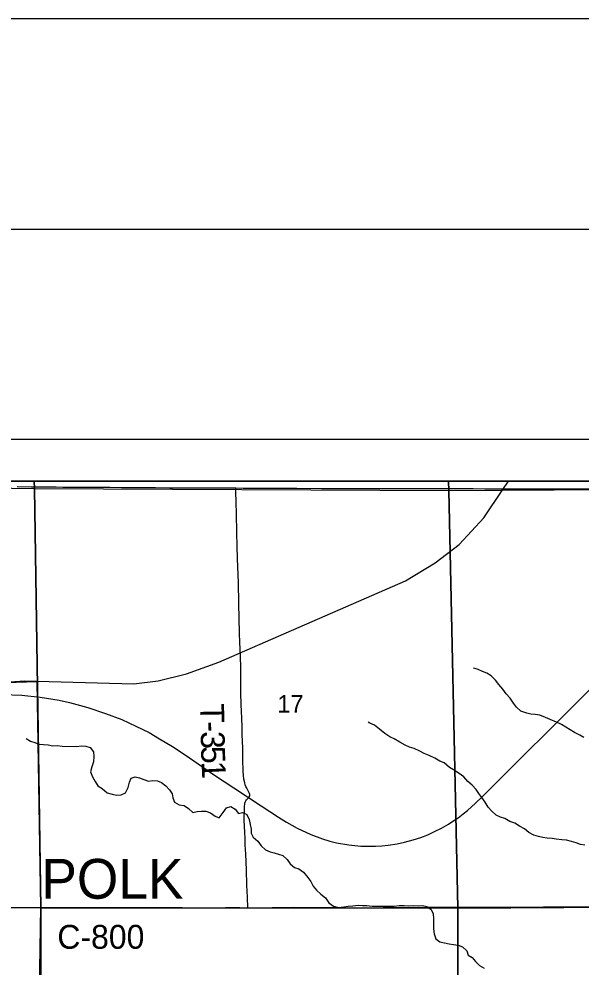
# Model space of a CAD drawing. Extents: x 0 to 34, y 0 to 22.
# Drawn here: x 4.028 to 5.364, y 19.744 to 22 of the extents above; entities that cross this region are included whole.
import ezdxf

# ---------------------------------------------------------------- set-up
doc = ezdxf.new("R2010")
doc.units = 0
for name, color, linetype in [('Default', 7, 'Continuous'), ('GM_X_Corporation', 7, 'Continuous'), ('GM_X_Corporation_Text', 7, 'Continuous'), ('GM_X_County_Road', 7, 'Continuous'), ('GM_X_County_Road_Text', 7, 'Continuous'), ('GM_X_Interstate_Route', 7, 'Continuous'), ('GM_X_Minor_River', 7, 'Continuous'), ('GM_X_Rail_Line', 7, 'Continuous'), ('GM_X_Section', 7, 'Continuous'), ('GM_X_Section_Text', 7, 'Continuous'), ('GM_X_Township_Road', 7, 'Continuous'), ('GM_X_Township_Road_Text', 7, 'Continuous'), ('SH_Border', 7, 'Continuous'), ('SH_Cut_Line', 7, 'Continuous'), ('SH_Data', 7, 'Continuous')]:
    doc.layers.add(name, color=color, linetype=linetype)

msp = doc.modelspace()

# ---------------------------------------------------------------- linework, layer by layer
at = {"layer": 'Default'}
for points in [[(4.0643, 20.9), (3.0341, 20.9), (3.0341, 20.898), (4.0647, 20.8827)], [(5.0488, 20.9), (4.0643, 20.9), (4.0647, 20.8827), (5.0494, 20.8782)], [(6.0512, 20.9), (5.0488, 20.9), (5.0494, 20.8782), (6.0515, 20.8843)]]:
    msp.add_lwpolyline(points, close=True, dxfattribs=at)
at = {"layer": 'GM_X_Corporation'}
msp.add_lwpolyline([(4.0712, 19.394), (3.5643, 19.3915), (3.0631, 19.3888), (3.0588, 19.9042), (3.0542, 20.415), (3.5567, 20.4072), (4.0701, 20.4238), (4.0786, 19.8867)], close=True, dxfattribs=at)
at = {"layer": 'GM_X_County_Road'}
for points in [[(4.0234, 20.8873), (4.0575, 20.8869), (4.0855, 20.8867), (4.1166, 20.8864), (4.1321, 20.8862), (4.1693, 20.8858), (4.2004, 20.8857), (4.2439, 20.8856), (4.2718, 20.8852), (4.2967, 20.885), (4.334, 20.8848), (4.3526, 20.8848), (4.3867, 20.8847), (4.4054, 20.8846), (4.4458, 20.8845), (4.5017, 20.8842), (4.5265, 20.8843), (4.5433, 20.8841)], [(4.5433, 20.8841), (4.5607, 20.8839), (4.5886, 20.8836), (4.6104, 20.8836), (4.6352, 20.8837), (4.688, 20.8832), (4.747, 20.883), (4.7905, 20.883), (4.8185, 20.8829), (4.8682, 20.8827), (4.9085, 20.8829), (4.9396, 20.8827), (5.0017, 20.8825), (5.0794, 20.8828), (5.1073, 20.8826), (5.1353, 20.8822), (5.1602, 20.8822), (5.1819, 20.882), (5.2005, 20.8819), (5.2316, 20.8823), (5.2595, 20.8823), (5.2968, 20.8822), (5.3403, 20.8821), (5.3838, 20.8819)], [(3.5641, 19.886), (3.5756, 19.8859), (3.5943, 19.886), (3.6161, 19.8861), (3.6566, 19.8863), (3.7251, 19.8868), (3.7624, 19.8868), (3.7935, 19.8869), (3.834, 19.8871), (3.8776, 19.8872), (3.9118, 19.8871), (3.9803, 19.8869), (4.0788, 19.8862)], [(4.0788, 19.8862), (4.0963, 19.8861), (4.1398, 19.8859), (4.1615, 19.8859), (4.2018, 19.886), (4.2422, 19.8859), (4.2981, 19.8859), (4.3756, 19.8855), (4.416, 19.8855), (4.478, 19.8854), (4.5184, 19.8855), (4.5525, 19.8855), (4.5719, 19.8854)], [(4.5719, 19.8854), (4.5835, 19.8853), (4.63, 19.886), (4.6797, 19.8866), (4.7944, 19.886), (4.8503, 19.8854), (4.8937, 19.8856), (4.9272, 19.8858), (4.9706, 19.886), (4.9955, 19.8863), (5.0141, 19.8864), (5.0482, 19.8864), (5.0698, 19.8867), (5.1008, 19.8866), (5.135, 19.8867), (5.166, 19.8869), (5.1847, 19.8868), (5.2747, 19.8873), (5.3057, 19.8876), (5.3243, 19.8876), (5.3491, 19.8875), (5.3771, 19.8876), (5.3988, 19.8875), (5.4225, 19.8877)]]:
    msp.add_lwpolyline(points, dxfattribs=at)
at = {"layer": 'GM_X_Interstate_Route'}
msp.add_lwpolyline([(8.1285, 16.8707), (8.1148, 17.8694), (8.0976, 18.2853), (8.0958, 18.3144), (8.0817, 18.88), (8.0959, 19.2713), (8.1023, 19.3817), (8.0929, 19.6339), (8.0678, 20.8562), (8.0675, 20.8733), (8.067, 20.8954), (8.0669, 20.9), (3.0331, 20.9), (3.0588, 19.9042), (3.067, 19.3838), (3.0747, 18.8969), (3.0724, 18.2926), (3.0939, 16.8719)], dxfattribs=at)
at = {"layer": 'GM_X_Minor_River'}
for points in [[(5.371, 20.2903), (5.3612, 20.2957), (5.3488, 20.3022), (5.3378, 20.3088), (5.3175, 20.3211), (5.3054, 20.3266), (5.2903, 20.3332), (5.2798, 20.3378), (5.2662, 20.3433), (5.2548, 20.3449), (5.2446, 20.3458), (5.2348, 20.3485), (5.2208, 20.3528), (5.2103, 20.3624), (5.2036, 20.372), (5.1957, 20.3842), (5.186, 20.3945), (5.1785, 20.4056), (5.1687, 20.4163), (5.1605, 20.427), (5.1503, 20.437), (5.1398, 20.4431), (5.1296, 20.4474), (5.1194, 20.4524), (5.1092, 20.4556), (5.1085, 20.4563)], [(5.373, 20.0338), (5.3628, 20.0358), (5.3526, 20.0397), (5.3416, 20.0428), (5.3292, 20.0463), (5.3182, 20.0472), (5.3053, 20.0488), (5.2951, 20.0501), (5.2837, 20.0509), (5.2732, 20.0522), (5.2633, 20.0546), (5.2516, 20.0577), (5.2403, 20.0639), (5.2294, 20.0727), (5.2181, 20.0793), (5.2068, 20.0862), (5.1947, 20.0901), (5.183, 20.0975), (5.1728, 20.101), (5.1619, 20.1056), (5.1518, 20.1148), (5.1435, 20.1244), (5.136, 20.1366), (5.1278, 20.1473), (5.1207, 20.1569), (5.1147, 20.1668), (5.105, 20.1767), (5.0952, 20.1859), (5.0854, 20.197), (5.0745, 20.2047), (5.061, 20.2132), (5.0512, 20.2186), (5.0388, 20.2298), (5.0282, 20.234), (5.0161, 20.2414), (5.0033, 20.2475), (4.9909, 20.2526), (4.9811, 20.2576), (4.9675, 20.2642), (4.9565, 20.2677), (4.9463, 20.2724), (4.9335, 20.279), (4.92, 20.2871), (4.9094, 20.2917), (4.8977, 20.2998), (4.8853, 20.3098), (4.8729, 20.3194), (4.8616, 20.3248), (4.8582, 20.3264)], [(4.0449, 20.2879), (4.0554, 20.2818), (4.0652, 20.2783), (4.0754, 20.2748), (4.0864, 20.2735), (4.097, 20.2726), (4.1083, 20.2706), (4.1186, 20.2713), (4.1307, 20.2693), (4.1655, 20.2689), (4.1754, 20.2704), (4.1867, 20.2699), (4.1969, 20.2664), (4.2051, 20.256), (4.2058, 20.2454), (4.2053, 20.2325), (4.2014, 20.2204), (4.1979, 20.2087), (4.2027, 20.1969), (4.2091, 20.1854), (4.2151, 20.1755), (4.2252, 20.169), (4.2373, 20.159), (4.249, 20.1555), (4.2596, 20.1531), (4.2709, 20.1541), (4.2808, 20.1586), (4.2877, 20.1714), (4.2909, 20.1839), (4.2944, 20.1937), (4.3042, 20.197), (4.3144, 20.1947), (4.3246, 20.19), (4.336, 20.1865), (4.3462, 20.1883), (4.3568, 20.187), (4.367, 20.1831), (4.3771, 20.1751), (4.3854, 20.1655), (4.3917, 20.156), (4.3939, 20.1465), (4.3976, 20.1366), (4.4089, 20.1304), (4.4203, 20.1284), (4.4308, 20.1214), (4.441, 20.1119), (4.4512, 20.114), (4.4618, 20.1151), (4.4724, 20.115), (4.483, 20.1111), (4.4939, 20.103), (4.5041, 20.0991), (4.5133, 20.1115), (4.521, 20.1228), (4.5316, 20.1265), (4.5414, 20.12), (4.5496, 20.1093), (4.5591, 20.1122), (4.5697, 20.1068), (4.5752, 20.095), (4.5778, 20.0836), (4.58, 20.0722), (4.5799, 20.0627), (4.5847, 20.0528), (4.5953, 20.0436), (4.6039, 20.0325), (4.614, 20.0233), (4.6246, 20.0186), (4.6344, 20.0159), (4.6446, 20.0128), (4.6552, 20.0092), (4.6653, 19.9997), (4.6728, 19.9901), (4.683, 19.9813), (4.6932, 19.9781), (4.7044, 19.9697), (4.7149, 19.9574), (4.7217, 19.9475), (4.7273, 19.9368), (4.7351, 19.9273), (4.7453, 19.9177), (4.7562, 19.9085), (4.7648, 19.897), (4.7757, 19.8893), (4.7874, 19.8862), (4.8003, 19.8872), (4.8102, 19.8886), (4.8219, 19.89), (4.8344, 19.8914), (4.8443, 19.8906), (4.8545, 19.8905), (4.8673, 19.8892), (4.8795, 19.8887), (4.8893, 19.889), (4.9098, 19.8888), (4.9196, 19.8891), (4.9317, 19.8905), (4.9438, 19.8903), (4.9541, 19.8895), (4.9651, 19.8905), (4.9772, 19.8896)], [(4.9772, 19.8896), (4.9874, 19.8903), (4.9972, 19.8879), (5.0081, 19.881), (5.0122, 19.8711), (5.0133, 19.8597), (5.0132, 19.8479), (5.0134, 19.835), (5.0145, 19.8233), (5.0189, 19.8115), (5.0287, 19.8038), (5.0397, 19.8018), (5.0502, 19.799), (5.0612, 19.7978), (5.0718, 19.7965), (5.0824, 19.7923), (5.0925, 19.783), (5.0958, 19.7724), (5.1056, 19.7666), (5.1135, 19.757), (5.1225, 19.7475), (5.1338, 19.7417)]]:
    msp.add_lwpolyline(points, dxfattribs=at)
at = {"layer": 'GM_X_Rail_Line'}
for points in [[(2.1, 19.1903), (2.2176, 19.2766), (2.3422, 19.3707), (2.5003, 19.4885), (2.7369, 19.665), (2.944, 19.8207), (3.3415, 20.1206), (3.4596, 20.2081), (3.5596, 20.3194), (3.7554, 20.3776), (3.8584, 20.4014), (3.9589, 20.4196), (4.0414, 20.4251), (4.3012, 20.4183), (4.3584, 20.4251), (4.4262, 20.4416), (4.5028, 20.4697), (4.9465, 20.6634), (5.0176, 20.7062), (5.0741, 20.7492), (5.1326, 20.8127), (5.1783, 20.8803), (5.1912, 20.9)], [(3.9898, 20.3929), (4.0344, 20.3908), (4.0784, 20.3866), (4.1232, 20.379), (4.1479, 20.3734), (4.1916, 20.3619), (4.2339, 20.3477), (4.2725, 20.3329), (4.306, 20.3176), (4.3371, 20.3019), (4.362, 20.2875), (4.3925, 20.2692), (4.423, 20.2491), (4.4927, 20.2005), (4.5383, 20.1707), (4.6036, 20.1278), (4.6446, 20.101), (4.664, 20.0891), (4.6894, 20.0743), (4.7214, 20.0593), (4.7491, 20.049), (4.7669, 20.0434), (4.7826, 20.0399), (4.8117, 20.0347), (4.8404, 20.0317), (4.8756, 20.0315), (4.8906, 20.0325), (4.9053, 20.0341), (4.9267, 20.0373), (4.9444, 20.0411), (4.965, 20.0467), (4.9829, 20.0525), (4.9999, 20.0591), (5.0159, 20.0664), (5.0321, 20.0744), (5.0488, 20.0843), (5.0595, 20.0909), (5.0717, 20.0992), (5.084, 20.1085), (5.0938, 20.1165), (5.1039, 20.1252), (5.1134, 20.134), (5.1293, 20.1489), (5.3848, 20.4049)]]:
    msp.add_lwpolyline(points, dxfattribs=at)
at = {"layer": 'GM_X_Section'}
for points in [[(4.0647, 20.8827), (4.0799, 19.8852), (3.0869, 19.8862), (3.0592, 19.8987), (3.0341, 20.898)], [(5.0494, 20.8782), (5.0715, 19.8844), (4.0799, 19.8852), (4.0647, 20.8827)], [(6.0515, 20.8843), (6.0796, 19.8902), (5.0715, 19.8844), (5.0494, 20.8782)], [(4.0799, 19.8852), (4.08, 18.8834), (3.073, 18.8909), (3.0592, 19.8987), (3.0869, 19.8862)], [(5.0715, 19.8844), (5.0689, 18.882), (4.08, 18.8834), (4.0799, 19.8852)], [(6.0796, 19.8902), (6.0998, 18.8817), (5.0689, 18.882), (5.0715, 19.8844)]]:
    msp.add_lwpolyline(points, close=True, dxfattribs=at)
at = {"layer": 'GM_X_Township_Road'}
msp.add_lwpolyline([(4.5719, 19.8854), (4.5709, 19.9107), (4.5698, 19.9386), (4.5684, 19.9758), (4.5669, 20.013), (4.5658, 20.0346), (4.5654, 20.0502), (4.5649, 20.0639), (4.5635, 20.0935), (4.5637, 20.1214), (4.564, 20.1276), (4.5644, 20.1307), (4.5649, 20.1338), (4.5658, 20.1368), (4.5671, 20.1396), (4.5689, 20.1421), (4.5733, 20.1465), (4.5753, 20.1488), (4.5768, 20.1515), (4.577, 20.1545), (4.5759, 20.1573), (4.5723, 20.1636), (4.5692, 20.1696), (4.5674, 20.1737), (4.5659, 20.1773), (4.5645, 20.1823), (4.5627, 20.191), (4.5616, 20.2003), (4.5606, 20.2098), (4.5598, 20.2377), (4.5597, 20.2655), (4.5587, 20.2966), (4.5582, 20.3149), (4.5575, 20.3367), (4.5568, 20.3523), (4.556, 20.3688), (4.5549, 20.3968), (4.555, 20.4172), (4.5549, 20.4422), (4.5551, 20.4545), (4.5542, 20.4855), (4.5527, 20.5165), (4.5519, 20.5382), (4.5507, 20.6095), (4.5499, 20.6592), (4.5483, 20.6965), (4.5477, 20.7164), (4.5465, 20.7459), (4.5459, 20.777), (4.5448, 20.8235), (4.5445, 20.8483), (4.5437, 20.8762), (4.5435, 20.8793), (4.5433, 20.8841)], dxfattribs=at)
at = {"layer": 'SH_Border'}
msp.add_lwpolyline([(1.5, 21.5), (33.5, 21.5), (33.5, 0.5), (1.5, 0.5)], close=True, dxfattribs=at)
at = {"layer": 'SH_Cut_Line'}
msp.add_lwpolyline([(0, 0), (34, 0), (34, 22), (0, 22)], close=True, dxfattribs=at)
msp.add_lwpolyline([(8.1285, 16.8707), (8.1148, 17.8694), (8.0976, 18.2853), (8.0958, 18.3144), (8.0817, 18.88), (8.0959, 19.2713), (8.1023, 19.3817), (8.0929, 19.6339), (8.0678, 20.8562), (8.0675, 20.8733), (8.067, 20.8954), (8.0669, 20.9), (2.1, 20.9), (2.1, 14.1)], dxfattribs=at)
at = {"layer": 'SH_Data'}
for p, q in [((2, 21), (9, 21)), ((2.1, 20.9), (8.9, 20.9))]:
    msp.add_line(p, q, dxfattribs=at)

# ---------------------------------------------------------------- texts
at = {"layer": 'GM_X_Corporation_Text'}
msp.add_text('POLK', height=0.0947, rotation=0, dxfattribs=at).set_placement((4.081, 19.9067))
at = {"layer": 'GM_X_County_Road_Text'}
msp.add_text('C-800', height=0.05682, rotation=0.0031, dxfattribs=at).set_placement((4.119, 19.7876))
at = {"layer": 'GM_X_Section_Text'}
msp.add_text('17', height=0.04186, rotation=0, dxfattribs=at).set_placement((4.6421, 20.3494))
at = {"layer": 'GM_X_Township_Road_Text'}
for s, rotation, p in [('T', 271.0629, (4.4585, 20.3709)), ('-', 271.0966, (4.4593, 20.3284)), ('3', 271.2356, (4.4597, 20.3049)), ('5', 271.6389, (4.4605, 20.2695)), ('1', 272.8113, (4.4616, 20.2332))]:
    msp.add_text(s, height=0.0568, rotation=rotation, dxfattribs=at).set_placement(p)

doc.saveas('drawing.dxf')
